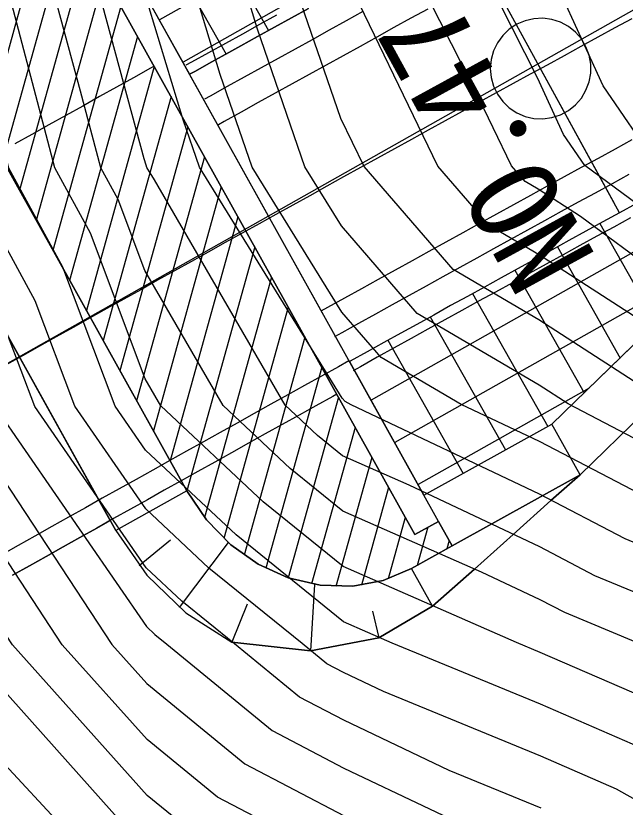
# Model space of a CAD drawing. Extents: x 42655 to 43811, y -141820 to -141156.
# Drawn here: x 43145.62 to 43161.36, y -141417.59 to -141397.14 of the extents above; entities that cross this region are included whole.
import ezdxf

# ---------------------------------------------------------------- set-up
doc = ezdxf.new("R2010")
doc.units = 0
for name, color, linetype in [('D-BMK-HTXT_1', 7, 'Continuous'), ('D-BMK_1', 7, 'Continuous'), ('D-STR', 7, 'Continuous'), ('D-STR-HTXT', 7, 'Continuous'), ('D-STR-STR2トンネル', 7, 'Continuous'), ('D-STR_1', 7, 'Continuous'), ('ZE_HICN', 7, 'Continuous'), ('ZE_LWCN', 7, 'Continuous'), ('着色', 7, 'Continuous')]:
    doc.layers.add(name, color=color, linetype=linetype)

msp = doc.modelspace()

# ---------------------------------------------------------------- linework, layer by layer
at = {"layer": 'D-BMK-HTXT_1'}
for p, q in [((43274.802, -141333.044), (43130.975, -141414.265)), ((43161.22, -141402.227), (43157.138, -141394.772)), ((43161.1, -141402.008), (43157.258, -141394.991))]:
    msp.add_line(p, q, dxfattribs=at)
for points in [[(43157.879, -141398.499), (43157.9, -141398.732), (43157.962, -141398.956), (43158.063, -141399.166), (43158.2, -141399.355), (43158.368, -141399.516), (43158.563, -141399.644), (43158.777, -141399.736), (43159.004, -141399.788), (43159.237, -141399.798), (43159.468, -141399.767), (43159.69, -141399.695), (43159.895, -141399.584), (43160.077, -141399.439), (43160.231, -141399.263), (43160.35, -141399.063), (43160.432, -141398.845), (43160.474, -141398.616), (43160.474, -141398.383), (43160.432, -141398.154), (43160.35, -141397.935), (43160.231, -141397.735), (43160.077, -141397.56), (43159.895, -141397.414), (43159.69, -141397.304), (43159.468, -141397.232), (43159.237, -141397.201), (43159.004, -141397.211), (43158.777, -141397.263), (43158.563, -141397.355), (43158.368, -141397.483), (43158.2, -141397.644), (43158.063, -141397.833), (43157.962, -141398.043), (43157.9, -141398.267), (43157.879, -141398.499)], [(43157.879, -141398.499), (43157.9, -141398.732), (43157.962, -141398.956), (43158.063, -141399.166), (43158.2, -141399.355), (43158.368, -141399.516), (43158.563, -141399.644), (43158.777, -141399.736), (43159.005, -141399.788), (43159.237, -141399.798), (43159.468, -141399.767), (43159.69, -141399.695), (43159.895, -141399.584), (43160.077, -141399.439), (43160.231, -141399.264), (43160.35, -141399.063), (43160.432, -141398.845), (43160.474, -141398.616), (43160.474, -141398.383), (43160.432, -141398.154), (43160.35, -141397.935), (43160.231, -141397.735), (43160.077, -141397.56), (43159.895, -141397.414), (43159.69, -141397.304), (43159.468, -141397.232), (43159.237, -141397.201), (43159.004, -141397.211), (43158.777, -141397.263), (43158.563, -141397.355), (43158.368, -141397.483), (43158.2, -141397.644), (43158.063, -141397.833), (43157.962, -141398.043), (43157.9, -141398.267), (43157.879, -141398.499)]]:
    msp.add_lwpolyline(points, dxfattribs=at)
at = {"layer": 'D-BMK_1'}
msp.add_lwpolyline([(43161.538, -141397.211), (43161.099, -141397.45), (43160.66, -141397.689), (43160.222, -141397.929), (43159.783, -141398.169), (43159.344, -141398.409), (43158.906, -141398.649), (43158.467, -141398.889), (43158.029, -141399.13), (43157.591, -141399.371), (43157.153, -141399.612), (43156.714, -141399.853), (43156.276, -141400.094), (43155.839, -141400.335), (43155.401, -141400.577), (43154.963, -141400.818), (43154.525, -141401.06), (43154.088, -141401.302), (43153.65, -141401.544), (43153.213, -141401.786), (43152.776, -141402.029), (43152.338, -141402.271), (43151.901, -141402.514), (43151.464, -141402.757), (43151.027, -141403), (43150.59, -141403.243), (43150.153, -141403.486), (43149.716, -141403.729), (43149.28, -141403.973), (43148.843, -141404.216), (43148.406, -141404.46), (43147.97, -141404.703), (43147.533, -141404.947), (43147.097, -141405.191), (43146.66, -141405.435), (43146.224, -141405.679), (43145.788, -141405.924), (43145.352, -141406.168)], dxfattribs=at)
at = {"layer": 'D-STR'}
for p, q in [((43156.538, -141410.204), (43147.784, -141394.476)), ((43155.926, -141410.544), (43147.172, -141394.817)), ((43169.978, -141397.482), (43159.469, -141407.69)), ((43169.862, -141399.605), (43160.199, -141409)), ((43145.025, -141400.418), (43150.035, -141409.418)), ((43148.2, -141410.439), (43143.191, -141401.439)), ((43156.163, -141409.53), (43159.469, -141407.69)), ((43160.199, -141409), (43159.469, -141407.69)), ((43156.892, -141410.841), (43160.199, -141409)), ((43150.035, -141409.418), (43148.2, -141410.439)), ((43155.926, -141410.544), (43156.538, -141410.204)), ((43156.538, -141410.204), (43156.892, -141410.841)), ((43149.617, -141410.69), (43148.803, -141411.355)), ((43151.104, -141410.751), (43149.837, -141412.428)), ((43155.844, -141411.424), (43156.892, -141410.841)), ((43156.384, -141412.394), (43155.844, -141411.424)), ((43153.338, -141411.835), (43153.229, -141413.547)), ((43151.596, -141412.348), (43151.196, -141413.323)), ((43154.831, -141412.524), (43154.994, -141413.211))]:
    msp.add_line(p, q, dxfattribs=at)
for points in [[(43153.182, -141396.947), (43152.743, -141397.189), (43152.304, -141397.432), (43151.865, -141397.675), (43151.427, -141397.917), (43151.12, -141398.087), (43150.682, -141398.33), (43150.243, -141398.573), (43150.107, -141398.649)], [(43161.657, -141401.988), (43161.22, -141402.227), (43160.783, -141402.466), (43160.346, -141402.706), (43159.91, -141402.946), (43159.473, -141403.186), (43159.036, -141403.426), (43158.599, -141403.666), (43158.163, -141403.907), (43157.726, -141404.148), (43157.29, -141404.388), (43156.853, -141404.629), (43156.417, -141404.871), (43155.981, -141405.112), (43155.565, -141405.342), (43155.129, -141405.584), (43154.693, -141405.825), (43154.257, -141406.067), (43154.241, -141406.076)], [(43160.199, -141409), (43159.44, -141409.663), (43158.466, -141410.548), (43157.473, -141411.444), (43156.384, -141412.394), (43154.994, -141413.211), (43153.229, -141413.547), (43151.196, -141413.323)], [(43150.035, -141409.418), (43150.543, -141410.166), (43151.176, -141410.813)], [(43148.2, -141410.439), (43148.998, -141411.595), (43150.01, -141412.569), (43151.196, -141413.323)], [(43151.176, -141410.813), (43151.877, -141411.308), (43152.658, -141411.662)], [(43154.327, -141411.879), (43155.11, -141411.734), (43155.844, -141411.424)], [(43152.658, -141411.662), (43153.482, -141411.856), (43154.327, -141411.879)]]:
    msp.add_lwpolyline(points, dxfattribs=at)
at = {"layer": 'D-STR-HTXT'}
for p, q in [((43149.947, -141398.324), (43163.574, -141390.629)), ((43149.339, -141397.232), (43158.71, -141391.94)), ((43147.177, -141394.04), (43145.277, -141400.87)), ((43150.281, -141394.212), (43152.148, -141397.518)), ((43146.41, -141394.467), (43144.85, -141400.072)), ((43149.11, -141394.681), (43151.054, -141398.124)), ((43147.464, -141395.341), (43145.71, -141401.647)), ((43147.897, -141396.118), (43146.142, -141402.424)), ((43148.329, -141396.895), (43146.575, -141403.201)), ((43148.762, -141397.672), (43147.007, -141403.979)), ((43149.194, -141398.449), (43147.44, -141404.756)), ((43149.627, -141399.226), (43147.872, -141405.533)), ((43150.059, -141400.003), (43148.305, -141406.31)), ((43154.81, -141407.062), (43167.499, -141399.897)), ((43150.492, -141400.781), (43148.738, -141407.087)), ((43150.925, -141401.558), (43149.17, -141407.864)), ((43151.357, -141402.335), (43149.603, -141408.641)), ((43160.708, -141402.508), (43162.161, -141405.082)), ((43151.79, -141403.112), (43150.035, -141409.419)), ((43159.612, -141403.109), (43161.234, -141405.982)), ((43155.418, -141408.154), (43163.969, -141403.326)), ((43158.516, -141403.712), (43160.307, -141406.883)), ((43152.222, -141403.889), (43150.493, -141410.104)), ((43157.422, -141404.316), (43159.361, -141407.75)), ((43152.655, -141404.666), (43150.991, -141410.647)), ((43156.328, -141404.92), (43158.269, -141408.358)), ((43153.087, -141405.443), (43151.519, -141411.08)), ((43155.234, -141405.525), (43157.177, -141408.966)), ((43153.52, -141406.221), (43152.075, -141411.414)), ((43156.026, -141409.247), (43160.439, -141406.755)), ((43153.952, -141406.998), (43152.655, -141411.661)), ((43154.385, -141407.775), (43153.259, -141411.821)), ((43154.817, -141408.552), (43153.889, -141411.888)), ((43155.25, -141409.329), (43154.547, -141411.856)), ((43155.682, -141410.106), (43155.241, -141411.692)), ((43156.261, -141410.358), (43155.987, -141411.345)), ((43156.815, -141410.701), (43156.754, -141410.917))]:
    msp.add_line(p, q, dxfattribs=at)
at = {"layer": 'D-STR-STR2トンネル'}
for points in [[(43149.19, -141398.442), (43149.097, -141398.494), (43148.658, -141398.738), (43148.22, -141398.982), (43147.782, -141399.225), (43147.344, -141399.469), (43146.906, -141399.713), (43146.468, -141399.957), (43146.031, -141400.202), (43145.593, -141400.446)], [(43154.224, -141406.056), (43153.951, -141406.207), (43153.515, -141406.449), (43153.079, -141406.692), (43152.643, -141406.934), (43152.208, -141407.177), (43151.772, -141407.419), (43151.336, -141407.662), (43150.9, -141407.905), (43150.465, -141408.148), (43150.029, -141408.392), (43149.593, -141408.635), (43149.158, -141408.878), (43148.722, -141409.122), (43148.287, -141409.366), (43147.851, -141409.609), (43147.416, -141409.853), (43146.98, -141410.097), (43146.545, -141410.341), (43146.11, -141410.586), (43145.674, -141410.83), (43145.239, -141411.074)], [(43153.908, -141406.918), (43153.807, -141406.974), (43153.371, -141407.216), (43152.935, -141407.458), (43152.499, -141407.701), (43152.064, -141407.944), (43151.628, -141408.186), (43151.192, -141408.429), (43150.757, -141408.672), (43150.321, -141408.915), (43149.886, -141409.159), (43149.45, -141409.402), (43149.015, -141409.646), (43148.58, -141409.889), (43148.144, -141410.133), (43147.709, -141410.377), (43147.274, -141410.621), (43146.838, -141410.865), (43146.403, -141411.109), (43145.968, -141411.353), (43145.533, -141411.597)]]:
    msp.add_lwpolyline(points, dxfattribs=at)
at = {"layer": 'D-STR_1'}
for points in [[(43154.588, -141397.028), (43154.149, -141397.27), (43153.71, -141397.512), (43153.271, -141397.755), (43152.832, -141397.997), (43152.394, -141398.239), (43151.955, -141398.482), (43151.517, -141398.725), (43151.078, -141398.968), (43150.64, -141399.211), (43150.492, -141399.293)], [(43156.266, -141396.961), (43155.827, -141397.202), (43155.388, -141397.443), (43154.949, -141397.685), (43154.511, -141397.927), (43154.072, -141398.169), (43153.634, -141398.411), (43153.195, -141398.653), (43152.757, -141398.896), (43152.318, -141399.138), (43151.88, -141399.381), (43151.442, -141399.624), (43151.004, -141399.867), (43150.853, -141399.951)], [(43152.349, -141397.122), (43151.91, -141397.364), (43151.471, -141397.607), (43151.032, -141397.85), (43150.594, -141398.093), (43150.155, -141398.336), (43150.012, -141398.416)], [(43161.54, -141400.342), (43161.102, -141400.582), (43160.665, -141400.821), (43160.227, -141401.061), (43159.79, -141401.301), (43159.352, -141401.541), (43158.915, -141401.781), (43158.478, -141402.021), (43158.041, -141402.262), (43157.603, -141402.502), (43157.166, -141402.743), (43156.73, -141402.984), (43156.293, -141403.226), (43155.856, -141403.467), (43155.419, -141403.708), (43154.982, -141403.95), (43154.546, -141404.192), (43154.109, -141404.434), (43153.673, -141404.676), (43153.495, -141404.775)], [(43161.462, -141401.24), (43161.025, -141401.479), (43160.588, -141401.718), (43160.15, -141401.958), (43159.713, -141402.198), (43159.276, -141402.438), (43158.839, -141402.678), (43158.402, -141402.919), (43157.965, -141403.159), (43157.529, -141403.4), (43157.092, -141403.641), (43156.655, -141403.882), (43156.219, -141404.123), (43155.782, -141404.365), (43155.346, -141404.606), (43154.909, -141404.848), (43154.473, -141405.09), (43154.037, -141405.332), (43153.855, -141405.433)], [(43161.505, -141402.356), (43161.068, -141402.596), (43160.631, -141402.835), (43160.194, -141403.075), (43159.758, -141403.315), (43159.321, -141403.555), (43158.884, -141403.795), (43158.448, -141404.035), (43158.011, -141404.276), (43157.575, -141404.517), (43157.139, -141404.757), (43156.702, -141404.999), (43156.266, -141405.24), (43155.83, -141405.481), (43155.394, -141405.723), (43154.958, -141405.964), (43154.522, -141406.206), (43154.335, -141406.31)]]:
    msp.add_lwpolyline(points, dxfattribs=at)
at = {"layer": 'ZE_HICN'}
for points in [[(43164.284, -141418.895), (43161.139, -141417.126), (43159.184, -141416.275), (43155.119, -141414.603), (43154.086, -141414.112), (43153.652, -141413.885), (43153.016, -141413.364), (43150.606, -141411.412), (43148.978, -141409.883), (43147.144, -141407.229), (43146.118, -141404.504), (43144.251, -141401.08), (43143.841, -141399.518), (43142.715, -141394.924), (43141.74, -141391.264), (43140.342, -141388.773), (43138.687, -141385.618), (43137.581, -141383.954), (43136.3, -141382.629)], [(43175.612, -141418.021), (43174.454, -141417.392), (43171.242, -141415.561), (43169.352, -141414.475), (43167.248, -141413.297), (43164.251, -141411.854), (43161.361, -141410.656), (43159.152, -141409.504), (43154.281, -141407.195), (43154.128, -141407.105), (43154.052, -141407.018), (43150.365, -141401.051), (43149.942, -141399.828), (43148.914, -141396.436), (43148.498, -141394.897), (43147.452, -141390.476), (43146.935, -141388.742), (43145.999, -141385.278), (43145.642, -141382.585)], [(43184.625, -141416.308), (43180.592, -141413.234), (43179.52, -141412.774), (43179.036, -141412.656), (43174.423, -141410.867), (43172.099, -141409.922), (43169.324, -141408.573), (43166.803, -141407.137), (43165.008, -141406.197), (43164.221, -141405.291), (43160.209, -141402.325), (43159.115, -141401.618), (43158.777, -141401.419), (43158.426, -141401.013), (43157.482, -141399.054), (43155.36, -141394.865), (43155.026, -141393.611), (43153.972, -141389.876), (43153.713, -141388.71), (43153.421, -141383.178)], [(43155.333, -141438.004), (43155.812, -141433.818), (43156.43, -141431.836), (43157.209, -141428.129), (43157.365, -141425.669), (43156.075, -141423.318), (43154.119, -141421.235), (43152.664, -141419.528), (43150.124, -141418.199), (43149.012, -141417.289), (43145.534, -141413.399), (43143.894, -141410.906), (43141.811, -141407.254), (43140.654, -141404.988), (43139.181, -141401.104), (43138.753, -141399.676), (43137.543, -141396.396), (43136.607, -141394.953)]]:
    msp.add_lwpolyline(points, dxfattribs=at)
at = {"layer": 'ZE_LWCN'}
for points in [[(43164.367, -141436.421), (43166.567, -141431.788), (43167.584, -141429.556), (43169.333, -141425.613), (43168.188, -141420.901), (43167.762, -141419.457), (43164.278, -141417.448), (43161.947, -141416.138), (43159.178, -141414.933), (43155.338, -141413.353), (43154.08, -141412.801), (43151.306, -141410.555), (43148.97, -141408.362), (43148.185, -141407.224), (43146.831, -141403.632), (43145.437, -141401.074), (43143.819, -141394.919), (43142.573, -141390.245), (43141.744, -141388.766), (43138.675, -141382.915), (43138.565, -141382.75), (43138.438, -141382.619), (43137.933, -141381.729), (43134.97, -141376.473)], [(43168.565, -141418.478), (43164.271, -141416.002), (43162.755, -141415.149), (43159.171, -141413.59), (43158.558, -141413.338), (43154.073, -141411.372), (43152.007, -141409.698), (43149.366, -141407.218), (43148.962, -141406.52), (43147.545, -141402.759), (43146.623, -141401.069), (43145.554, -141397), (43144.989, -141394.914), (43144.727, -141393.808), (43143.799, -141390.698), (43143.407, -141389.225), (43143.145, -141388.76), (43142.047, -141386.665), (43140.369, -141382.61)], [(43172.827, -141419.434), (43169.366, -141417.445), (43166.249, -141415.7), (43164.264, -141414.555), (43163.563, -141414.161), (43161.638, -141413.323), (43159.802, -141412.563), (43159.165, -141412.231), (43157.652, -141411.514), (43154.066, -141409.942), (43152.708, -141408.842), (43150.971, -141407.211), (43148.949, -141403.719), (43148.258, -141401.887), (43147.809, -141401.063), (43147.288, -141399.081), (43146.158, -141394.908), (43145.636, -141392.698), (43144.459, -141388.753), (43143.778, -141386.236), (43142.275, -141382.601)], [(43182.972, -141425.549), (43181.453, -141423.274), (43179.684, -141419.401), (43179.551, -141419.285), (43176.457, -141416.988), (43174.447, -141415.896), (43169.866, -141413.285), (43169.477, -141413.127), (43169.345, -141413.063), (43168.991, -141412.861), (43164.245, -141410.575), (43162.14, -141409.703), (43159.146, -141408.141), (43157.123, -141407.182), (43155.058, -141405.968), (43154.042, -141404.794), (43151.725, -141401.045), (43150.9, -141398.656), (43149.76, -141394.891), (43148.892, -141391.612), (43148.361, -141389.366), (43148.173, -141388.736), (43147.833, -141387.479), (43147.184, -141382.578)], [(43183.467, -141419.384), (43179.535, -141415.954), (43178.146, -141414.923), (43175.087, -141413.26), (43174.433, -141413.007), (43170.788, -141411.524), (43169.335, -141410.818), (43165.437, -141408.598), (43164.233, -141408.018), (43163.699, -141407.797), (43162.473, -141407.157), (43159.131, -141404.995), (43156.918, -141403.694), (43154.615, -141401.031), (43154.018, -141399.793), (43152.817, -141396.313), (43152.382, -141394.879), (43151.629, -141392.033), (43150.894, -141388.723), (43150.772, -141386.417), (43150.264, -141382.564)], [(43182.714, -141417.068), (43179.527, -141414.289), (43178.99, -141413.89), (43177.808, -141413.247), (43174.428, -141411.937), (43171.443, -141410.723), (43169.329, -141409.695), (43164.853, -141407.146), (43164.418, -141406.918), (43164.227, -141406.698), (43163.255, -141405.979), (43159.123, -141403.306), (43157.848, -141402.557), (43156.521, -141401.022), (43154, -141395.792), (43153.775, -141395.141), (43153.694, -141394.873), (43153.553, -141394.341), (43152.303, -141388.717), (43152.096, -141384.797), (43151.801, -141382.556)], [(43183.483, -141413.221), (43179.514, -141411.516), (43177.72, -141411.077), (43174.418, -141409.797), (43172.754, -141409.12), (43169.319, -141407.45), (43168.752, -141407.127), (43165.597, -141405.476), (43164.214, -141403.884), (43160.318, -141401.004), (43159.77, -141400.205), (43159.102, -141398.743), (43157.133, -141394.857), (43156.364, -141391.975), (43155.441, -141388.702), (43155.129, -141383.975), (43155.038, -141382.541)], [(43183.616, -141412.023), (43179.508, -141410.259), (43176.405, -141409.499), (43174.413, -141408.727), (43173.409, -141408.319), (43170.937, -141407.117), (43169.314, -141406.392), (43166.187, -141404.755), (43164.207, -141402.477), (43162.203, -141400.995), (43160.799, -141398.948), (43159.085, -141395.202), (43158.906, -141394.848), (43157.703, -141390.338), (43157.238, -141388.693), (43157.082, -141386.318), (43156.842, -141382.533)], [(43173.611, -141418.403), (43169.359, -141415.96), (43164.625, -141413.309), (43164.257, -141413.132), (43160.581, -141411.61), (43159.159, -141410.867), (43155.778, -141409.265), (43154.059, -141408.512), (43153.409, -141407.985), (43152.577, -141407.203), (43149.2, -141401.374), (43149.004, -141401.057), (43148.984, -141400.999), (43148.935, -141400.838), (43147.328, -141394.903), (43146.544, -141391.587), (43145.697, -141388.748), (43144.165, -141383.078)], [(43182.669, -141421.787), (43181.575, -141419.392), (43179.543, -141417.62), (43177.301, -141415.956), (43174.44, -141414.4), (43172.461, -141413.273), (43170.133, -141412.326), (43169.34, -141411.94), (43167.214, -141410.729), (43164.239, -141409.297), (43162.92, -141408.75), (43159.89, -141407.169), (43159.139, -141406.683), (43155.988, -141404.831), (43154.031, -141402.569), (43153.086, -141401.038), (43151.859, -141397.484), (43151.071, -141394.885), (43149.705, -141389.725), (43149.484, -141388.73), (43149.448, -141388.036), (43148.854, -141383.537)], [(43159.19, -141417.618), (43156.819, -141416.642), (43154.091, -141415.347), (43152.946, -141414.748), (43151.267, -141413.372), (43149.905, -141412.269), (43148.985, -141411.405), (43146.104, -141407.234), (43145.404, -141405.377), (43143.855, -141402.534), (43143.396, -141401.635), (43143.187, -141401.085), (43142.815, -141399.843), (43141.612, -141394.93), (43140.906, -141392.283), (43138.94, -141388.779), (43138.7, -141388.321), (43136.596, -141385.158)], [(43135.612, -141386.361), (43137.226, -141388.787), (43138.712, -141390.877), (43140.073, -141393.302), (43140.508, -141394.935), (43141.25, -141397.965), (43142.185, -141401.09), (43142.71, -141402.473), (43143.865, -141404.735), (43144.691, -141406.25), (43145.063, -141407.239), (43148.992, -141412.926), (43149.204, -141413.126), (43149.519, -141413.38), (43152.241, -141415.611), (43154.097, -141416.582), (43158.519, -141418.682)], [(43135.447, -141388.796), (43138.724, -141393.402), (43139.24, -141394.321), (43139.404, -141394.94), (43139.686, -141396.088), (43141.184, -141401.094), (43142.025, -141403.311), (43143.876, -141406.936), (43143.977, -141407.122), (43144.023, -141407.244), (43144.73, -141408.267), (43148.097, -141413.387), (43148.999, -141414.396), (43151.535, -141416.474), (43154.103, -141417.817), (43157.657, -141419.505), (43158.478, -141420.379), (43159.21, -141421.712), (43161.074, -141425.651), (43160.551, -141427.247), (43159.64, -141431.821), (43159.263, -141433.096), (43158.159, -141436.634)], [(43156.669, -141437.998), (43156.986, -141435.226), (43158.046, -141431.828), (43159.231, -141426.186), (43159.315, -141425.764), (43159.349, -141425.66), (43159.227, -141425.402), (43157.276, -141421.849), (43155.088, -141419.517), (43154.109, -141419.052), (43150.829, -141417.337), (43149.006, -141415.842), (43146.815, -141413.393), (43143.885, -141408.937), (43142.922, -141407.249), (43141.339, -141404.15), (43140.182, -141401.099), (43138.737, -141396.271), (43138.398, -141395.351), (43138.135, -141394.946), (43133.98, -141389.243)], [(43154.19, -141436.328), (43154.638, -141432.41), (43154.815, -141431.844), (43155.038, -141430.785), (43155.362, -141425.678), (43154.873, -141424.788), (43154.132, -141423.998), (43150.33, -141419.539), (43149.418, -141419.062), (43149.019, -141418.735), (43144.252, -141413.405), (43143.903, -141412.875), (43140.7, -141407.259), (43139.968, -141405.826), (43138.767, -141402.66), (43138.042, -141401.109), (43136.689, -141397.441), (43135.079, -141394.96)], [(43151.344, -141438.023), (43152.145, -141434.321), (43152.818, -141431.853), (43152.936, -141430.367), (43153.27, -141425.688), (43149.028, -141420.709), (43148.539, -141420.137), (43148.162, -141419.549), (43143.913, -141414.963), (43143.493, -141414.42), (43143.275, -141414.179), (43142.966, -141413.411), (43141.33, -141410.316), (43139.589, -141407.264), (43139.283, -141406.665), (43138.78, -141405.339), (43136.804, -141401.115), (43135.834, -141398.486)]]:
    msp.add_lwpolyline(points, dxfattribs=at)
at = {"layer": '着色'}
for p, q in [((43150.035, -141409.418), (43150.035, -141409.418)), ((43151.176, -141410.813), (43151.176, -141410.813)), ((43151.176, -141410.813), (43151.176, -141410.813)), ((43152.658, -141411.662), (43152.658, -141411.662)), ((43152.658, -141411.662), (43152.658, -141411.662)), ((43154.327, -141411.879), (43154.327, -141411.879)), ((43154.327, -141411.879), (43154.327, -141411.879))]:
    msp.add_line(p, q, dxfattribs=at)
for points in [[(43155.844, -141411.424), (43155.844, -141411.424), (43156.892, -141410.841), (43156.538, -141410.204), (43155.926, -141410.544), (43147.172, -141394.817), (43147.78, -141394.479), (43147.451, -141393.887), (43146.394, -141394.476), (43146.394, -141394.476)], [(43148.185, -141395.196), (43150.107, -141398.649), (43150.243, -141398.573), (43150.682, -141398.33), (43151.12, -141398.087), (43151.427, -141397.917), (43151.865, -141397.675), (43152.304, -141397.432), (43152.743, -141397.189), (43153.182, -141396.947)], [(43161.657, -141401.988), (43161.22, -141402.227), (43160.783, -141402.466), (43160.346, -141402.706), (43159.91, -141402.946), (43159.473, -141403.186), (43159.036, -141403.426), (43158.599, -141403.666), (43158.163, -141403.907), (43157.726, -141404.148), (43157.29, -141404.388), (43156.853, -141404.629), (43156.417, -141404.871), (43155.981, -141405.112), (43155.565, -141405.342), (43155.129, -141405.584), (43154.693, -141405.825), (43154.257, -141406.067), (43154.241, -141406.076), (43156.163, -141409.53), (43159.469, -141407.69), (43169.978, -141397.482)], [(43150.035, -141409.418), (43150.035, -141409.418), (43145.025, -141400.418), (43145.025, -141400.418)], [(43145.025, -141400.418), (43145.025, -141400.418), (43150.035, -141409.418)], [(43143.191, -141401.439), (43143.191, -141401.439), (43148.2, -141410.439), (43148.2, -141410.439)], [(43145.533, -141411.597), (43145.968, -141411.353), (43146.403, -141411.109), (43146.838, -141410.865), (43147.274, -141410.621), (43147.709, -141410.377), (43148.057, -141410.182), (43143.339, -141401.706)], [(43151.196, -141413.323), (43151.196, -141413.323), (43153.229, -141413.547), (43154.994, -141413.211), (43156.384, -141412.394), (43157.473, -141411.444), (43158.466, -141410.548), (43159.44, -141409.663), (43160.199, -141409), (43156.892, -141410.841), (43155.844, -141411.424), (43155.844, -141411.424)], [(43151.176, -141410.813), (43150.543, -141410.166), (43150.035, -141409.418)], [(43150.035, -141409.418), (43150.543, -141410.166), (43151.176, -141410.813)], [(43148.2, -141410.439), (43148.998, -141411.595), (43150.01, -141412.569), (43151.196, -141413.323)], [(43152.658, -141411.662), (43151.877, -141411.308), (43151.176, -141410.813)], [(43151.176, -141410.813), (43151.877, -141411.308), (43152.658, -141411.662)], [(43155.844, -141411.424), (43155.11, -141411.734), (43154.327, -141411.879)], [(43154.327, -141411.879), (43155.11, -141411.734), (43155.844, -141411.424)], [(43154.327, -141411.879), (43153.482, -141411.856), (43152.658, -141411.662)], [(43152.658, -141411.662), (43153.482, -141411.856), (43154.327, -141411.879)]]:
    msp.add_lwpolyline(points, dxfattribs=at)
msp.add_lwpolyline([(43155.926, -141410.544), (43156.538, -141410.204), (43147.784, -141394.476), (43147.172, -141394.817)], close=True, dxfattribs=at)

# ---------------------------------------------------------------- texts
at = {"layer": 'D-BMK-HTXT_1'}
msp.add_text('NO.47', height=2.3065, rotation=118.7056, dxfattribs=at).set_placement((43160.638, -141403.401))

doc.saveas('drawing.dxf')
